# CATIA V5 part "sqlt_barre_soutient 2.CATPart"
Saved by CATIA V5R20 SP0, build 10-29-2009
Part number: sqlt_barre_soutient 2
Publications: "longueur_barre_soutient 2", "hauteur_pivot_soutient", "rayon_pivot_soutient", "plan dessin", "Point.1", "axe de rotation", "Point.2", "Point.3", "plan début barre", "plan haut pivot", "Point.4", "Point.5", "Point.6", "Point.7", "longueur_jusqua_pivot_soutient", "Plan.5"
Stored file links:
  D:\ecole\thinkmotion\sqlt_barre_soutient 2.CATPart
  D:\ecole\thinkmotion\sqlt_eolienne.CATProduct
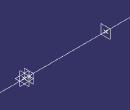
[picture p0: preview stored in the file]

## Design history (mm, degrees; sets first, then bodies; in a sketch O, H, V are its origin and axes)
Parameters
  `longueur_barre_soutient 2` = 2000 mm {= External.longueur_barre_soutient}
  hauteur_pivot_soutient = 20 mm {= External.hauteur_pivot_soutient}
  `rayon_pivot_soutient-rayon barre` = 15 mm {= External.rayon_pivot_soutient -External.rayon_barre}
  longueur_jusqua_pivot_soutient = 100 mm {= External.longueur_jusque_pivot_soutient}
External parameters (linked from other documents)
  `External.diamètre_trou` = 40 mm
  External.hauteur_pale = 2000 mm
  External.longueur_barre_soutient = 2000 mm
  External.hauteur_pivot_soutient = 20 mm
  External.rayon_pivot_soutient = 35 mm
  External.rayon_barre = 20 mm
  External.longueur_jusque_pivot_soutient = 100 mm
Body1 (main body)
  Plane1 "plan dessin": type Offset, RefPlane xy-plane, Offset 0
  Point1: (0, 0, 0)
  Line1 "axe de rotation": type PtDir, RefPoint Point1, Direction yz-plane, Start 0, End 20
  Point2: (0 {= 0}, 0, 0)
  Point3: (-2300 {= -External.hauteur_pale -300mm}, 0, 0)
  Plane2 "plan début barre": type Offset, RefPlane yz-plane, Offset 0
  Plane3 "plan haut pivot": type Offset, RefPlane yz-plane, Offset -2300 {= -External.hauteur_pale -300mm}
  Point4: (-100 {= -longueur_jusqua_pivot_soutient}, 35 {= `External.diamètre_trou`/2 +`rayon_pivot_soutient-rayon barre`}, 0)
  Point5: (-120 {= -(longueur_jusqua_pivot_soutient +hauteur_pivot_soutient )}, 20 {= `External.diamètre_trou` /2}, 0)
  Point6: (-2300 {= -External.hauteur_pale -300mm}, 20 {= `External.diamètre_trou` /2}, 0)
  Point7: (0, -20 {= -`External.diamètre_trou` /2}, 0)
  Plane4: type Offset, RefPlane Plane2, Offset -120 {= -hauteur_pivot_soutient -longueur_jusqua_pivot_soutient}
  Plane5: type Offset, RefPlane zx-plane, Offset 0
